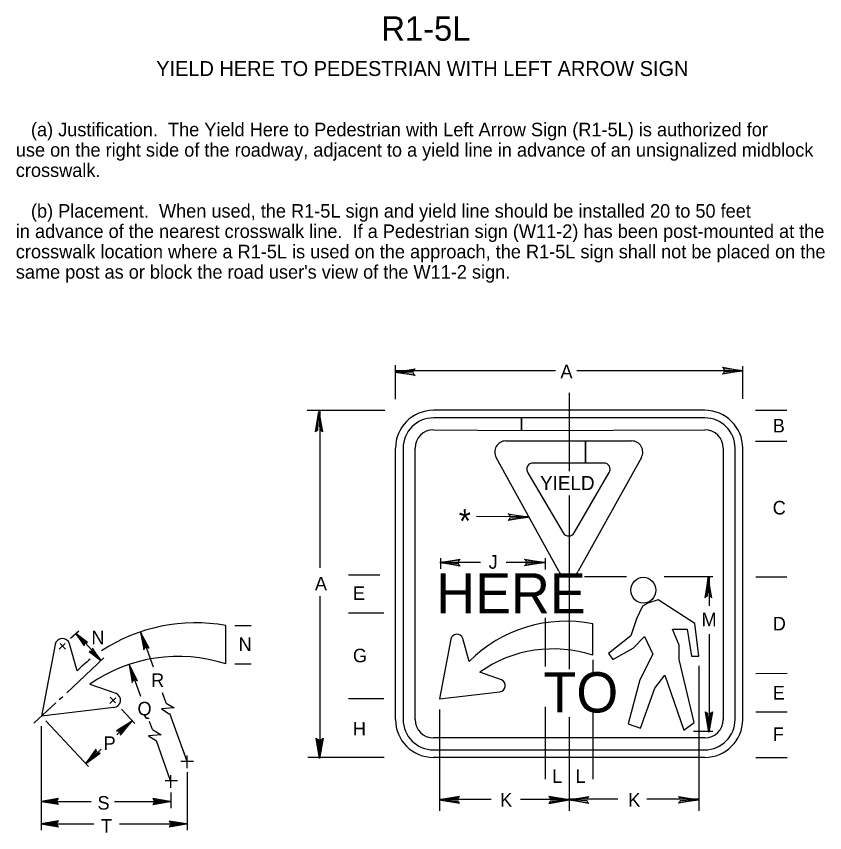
# Model space of a CAD drawing. Extents: x 0.013 to 0.186, y 0.004 to 0.259.
# Drawn here: x 0.0347 to 0.1837, y 0.1087 to 0.2593 of the extents above; entities that cross this region are included whole.
import ezdxf

# ---------------------------------------------------------------- set-up
doc = ezdxf.new("R2010")
doc.units = 0
for name, color, linetype in [('1', 7, 'Continuous'), ('2', 7, 'Continuous'), ('3', 7, 'Continuous')]:
    doc.layers.add(name, color=color, linetype=linetype)

# ---------------------------------------------------------------- blocks, each defined once
blk = doc.blocks.new('RARROW')
at = {"layer": '3'}
for p, q in [((-2.156, 0.28500000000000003), (-2.2665, 0.384625)), ((-2.2665, 0.384625), (0, 0)), ((0, 0), (-2.2665, -0.379125)), ((-2.156, 0.28500000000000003), (-2.075625, 0.12075)), ((0, 0), (-2.156, 0.28500000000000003)), ((-2.14975, -0.2705), (0, 0)), ((-2.075625, 0.12075), (0, 0)), ((0, 0), (-2.074, -0.108)), ((-2.2665, -0.379125), (-2.14975, -0.2705)), ((-2.074, -0.108), (-2.14975, -0.2705))]:
    blk.add_line(p, q, dxfattribs=at)

msp = doc.modelspace()

# ---------------------------------------------------------------- linework, layer by layer
at = {"layer": '1'}
for p, q in [((0.1365621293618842, 0.18985260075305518), (0.1365621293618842, 0.17539631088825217)), ((0.0906959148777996, 0.15757091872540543), (0.0906959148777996, 0.18659299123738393)), ((0.1615621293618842, 0.1866023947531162), (0.11156212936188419, 0.1866023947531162)), ((0.12776248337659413, 0.1852023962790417), (0.11156212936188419, 0.1852023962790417)), ((0.12776248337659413, 0.18290239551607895), (0.12776248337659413, 0.1852023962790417)), ((0.1615621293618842, 0.1852023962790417), (0.12776248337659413, 0.1852023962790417)), ((0.12776248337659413, 0.1852023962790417), (0.12776248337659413, 0.18290239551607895)), ((0.11156212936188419, 0.18300239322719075), (0.12776248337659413, 0.18290239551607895)), ((0.12776248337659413, 0.18290239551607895), (0.1615621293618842, 0.18300239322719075)), ((0.12489039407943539, 0.18096151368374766), (0.13957514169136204, 0.18096151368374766)), ((0.13957514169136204, 0.18096151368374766), (0.13957514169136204, 0.1768695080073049)), ((0.13957514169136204, 0.1768695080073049), (0.13957514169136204, 0.18096151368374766)), ((0.13957514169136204, 0.18096151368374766), (0.14808746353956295, 0.18096151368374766)), ((0.10456212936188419, 0.12960239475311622), (0.10456212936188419, 0.1796023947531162)), ((0.10596212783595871, 0.1796023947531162), (0.10596212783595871, 0.12960239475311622)), ((0.10816213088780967, 0.12960239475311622), (0.10816213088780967, 0.1796023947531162)), ((0.1649621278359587, 0.1796023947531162), (0.1649621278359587, 0.12960239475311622)), ((0.16716213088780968, 0.12960239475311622), (0.16716213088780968, 0.1796023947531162)), ((0.1685621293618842, 0.12960239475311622), (0.1685621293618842, 0.1796023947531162)), ((0.1346517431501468, 0.15693576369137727), (0.12309730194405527, 0.1779277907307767)), ((0.1498773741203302, 0.177922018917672), (0.13823473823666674, 0.15692999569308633)), ((0.13957514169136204, 0.1768695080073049), (0.12993006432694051, 0.1768695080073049)), ((0.1429629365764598, 0.1768695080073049), (0.13957514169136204, 0.1768695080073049)), ((0.12892390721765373, 0.1751062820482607), (0.13548238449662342, 0.16400731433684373)), ((0.13749802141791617, 0.16401299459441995), (0.14397241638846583, 0.17511195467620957)), ((0.1365621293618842, 0.17086639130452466), (0.1365621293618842, 0.1388963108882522)), ((0.11286213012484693, 0.15933980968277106), (0.11286213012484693, 0.15737611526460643)), ((0.13216213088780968, 0.15933980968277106), (0.13216213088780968, 0.15722883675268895)), ((0.16235171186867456, 0.15588100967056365), (0.16235171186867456, 0.1505340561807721)), ((0.0906959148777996, 0.12258233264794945), (0.0906959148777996, 0.15234443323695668)), ((0.13216213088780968, 0.14833527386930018), (0.13216213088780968, 0.13935383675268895)), ((0.07329347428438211, 0.13984812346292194), (0.07329347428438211, 0.14692309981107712)), ((0.1409621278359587, 0.14142676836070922), (0.1409621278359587, 0.14725513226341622)), ((0.04469179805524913, 0.1445622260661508), (0.0461749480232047, 0.14594528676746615)), ((0.045695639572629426, 0.14549832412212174), (0.050360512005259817, 0.14049586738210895)), ((0.059953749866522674, 0.1392708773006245), (0.05764195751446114, 0.14578228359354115)), ((0.11813826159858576, 0.14031910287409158), (0.11695585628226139, 0.14453414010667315)), ((0.16235171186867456, 0.14530286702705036), (0.16235171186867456, 0.1273809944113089)), ((0.04183427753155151, 0.1434092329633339), (0.03933348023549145, 0.13021299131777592)), ((0.04256482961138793, 0.14257878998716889), (0.043664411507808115, 0.14360417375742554)), ((0.04276641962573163, 0.14359910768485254), (0.043747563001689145, 0.14254696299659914)), ((0.04588771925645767, 0.13857995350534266), (0.04448595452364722, 0.14357697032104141)), ((0.11474613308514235, 0.14439435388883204), (0.11266213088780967, 0.13339748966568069)), ((0.04396765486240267, 0.13453443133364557), (0.0508398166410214, 0.14094282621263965)), ((0.1409621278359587, 0.14056803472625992), (0.1409621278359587, 0.13772883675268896)), ((0.05761690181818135, 0.13382880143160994), (0.055511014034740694, 0.1397602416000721)), ((0.1604621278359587, 0.13950189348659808), (0.1604621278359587, 0.11275311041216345)), ((0.12407117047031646, 0.13690389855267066), (0.12009439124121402, 0.13832543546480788)), ((0.048252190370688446, 0.13612652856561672), (0.053024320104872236, 0.1344206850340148)), ((0.06231665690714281, 0.1326155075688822), (0.06165305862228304, 0.13448459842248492)), ((0.11266213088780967, 0.13339748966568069), (0.12377758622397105, 0.1347093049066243)), ((0.037914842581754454, 0.12889009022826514), (0.04193633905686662, 0.1326401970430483)), ((0.042594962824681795, 0.13325437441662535), (0.04322944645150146, 0.13384604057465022)), ((0.05189458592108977, 0.132573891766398), (0.05299416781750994, 0.13359927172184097)), ((0.051968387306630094, 0.1337312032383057), (0.052982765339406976, 0.132643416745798)), ((0.052672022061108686, 0.1317871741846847), (0.03933348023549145, 0.13021299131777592)), ((0.054042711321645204, 0.13150676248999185), (0.05651857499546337, 0.12885172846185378)), ((0.11266213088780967, 0.13141330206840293), (0.11266213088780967, 0.11275311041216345)), ((0.13216213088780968, 0.1319339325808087), (0.13216213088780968, 0.11860383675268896)), ((0.1409621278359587, 0.13131318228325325), (0.1409621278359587, 0.11860383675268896)), ((0.06614082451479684, 0.12184433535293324), (0.06300259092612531, 0.13068349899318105)), ((0.1365621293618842, 0.1300407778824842), (0.1365621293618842, 0.11860383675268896)), ((0.03933348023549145, 0.10920893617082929), (0.03933348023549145, 0.12837398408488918)), ((0.040123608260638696, 0.12936567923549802), (0.04800561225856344, 0.12091326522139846)), ((0.053183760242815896, 0.12677003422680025), (0.056005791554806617, 0.1294016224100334)), ((0.05978366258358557, 0.12772589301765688), (0.05925541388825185, 0.1292137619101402)), ((0.06306558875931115, 0.1184819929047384), (0.060522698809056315, 0.12564431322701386)), ((0.1615621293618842, 0.1262023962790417), (0.11156212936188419, 0.1262023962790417)), ((0.04749282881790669, 0.12146315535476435), (0.0503365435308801, 0.12411496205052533)), ((0.06614082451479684, 0.12184433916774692), (0.0653419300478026, 0.12409451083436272)), ((0.11156212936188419, 0.12400239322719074), (0.1615621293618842, 0.12400239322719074)), ((0.06614082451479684, 0.12064433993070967), (0.06614082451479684, 0.12295720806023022)), ((0.1615621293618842, 0.12260239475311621), (0.11156212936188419, 0.12260239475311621)), ((0.06734082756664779, 0.12184433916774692), (0.06502795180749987, 0.12184433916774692)), ((0.06314082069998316, 0.11699781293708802), (0.06314082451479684, 0.11931068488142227)), ((0.06614082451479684, 0.11988760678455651), (0.06614082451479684, 0.10920893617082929)), ((0.06441310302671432, 0.11827009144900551), (0.06210022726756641, 0.11827009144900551)), ((0.1365621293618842, 0.11860383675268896), (0.1365621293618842, 0.11275311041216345)), ((0.06314082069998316, 0.11610695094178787), (0.06314082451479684, 0.11323927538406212)), ((0.04846923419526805, 0.11440763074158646), (0.03933348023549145, 0.11440763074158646)), ((0.06314082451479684, 0.11440763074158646), (0.05279922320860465, 0.11440763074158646)), ((0.04896923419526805, 0.11028890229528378), (0.03933348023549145, 0.11028890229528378)), ((0.06614082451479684, 0.11028890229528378), (0.05367884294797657, 0.11028890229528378))]:
    msp.add_line(p, q, dxfattribs=at)
for points in [[(0.06231665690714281, 0.1326155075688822), (0.06378179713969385, 0.1317367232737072), (0.06141981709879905, 0.131589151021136), (0.06288038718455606, 0.13064011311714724)], [(0.05978366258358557, 0.12772589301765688), (0.06140349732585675, 0.12675432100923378), (0.05904151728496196, 0.1266067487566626), (0.060522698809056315, 0.12564431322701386)]]:
    msp.add_lwpolyline(points, dxfattribs=at)
for centre, radius, start, end in [((0.11156213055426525, 0.1796023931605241), 0.007, 90, 180), ((0.11156213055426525, 0.1796023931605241), 0.005599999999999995, 90, 180), ((0.16156213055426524, 0.1796023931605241), 0.007, 0, 90), ((0.16156213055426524, 0.1796023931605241), 0.005599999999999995, 0, 90), ((0.11156213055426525, 0.1796023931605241), 0.003400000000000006, 90, 180), ((0.16156213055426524, 0.1796023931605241), 0.003400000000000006, 0, 90), ((0.12489039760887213, 0.17891474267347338), 0.002046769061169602, 89.99999999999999, 208.829273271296), ((0.1480874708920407, 0.17891474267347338), 0.0020467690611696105, 330.9862922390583, 90), ((0.12993006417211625, 0.17570081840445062), 0.0011686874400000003, 90, 210.57922687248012), ((0.14296293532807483, 0.17570081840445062), 0.001168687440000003, 329.74356283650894, 90), ((0.13648854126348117, 0.16460185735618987), 0.0011686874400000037, 210.57922480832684, 329.7435707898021), ((0.13644483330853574, 0.15792271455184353), 0.0020467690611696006, 208.82927195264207, 330.9862956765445), ((0.13610994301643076, 0.12220145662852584), 0.025519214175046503, 79.03913091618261, 134.76826429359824), ((0.067662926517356, 0.11623536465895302), 0.031200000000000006, 79.60307759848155, 123.5783292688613), ((0.04318157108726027, 0.14315390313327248), 0.001371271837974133, 17.969864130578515, 169.26922826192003), ((0.11586887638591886, 0.14418158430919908), 0.0011427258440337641, 17.97008397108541, 169.26922826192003), ((0.13361383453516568, 0.11911439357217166), 0.023491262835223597, 71.771363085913, 125.13531244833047), ((0.067662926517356, 0.11623536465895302), 0.031200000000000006, 128.37705113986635, 134.26062747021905), ((0.06453637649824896, 0.1126638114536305), 0.028560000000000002, 72.14427943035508, 124.76240248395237), ((0.1236436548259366, 0.1358441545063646), 0.001142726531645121, 276.73076526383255, 68.03012939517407), ((0.05251130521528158, 0.13314898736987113), 0.001371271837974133, 276.7307671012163, 68.03013123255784), ((0.11156213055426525, 0.12960239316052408), 0.007, 180, 270), ((0.11156213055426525, 0.12960239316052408), 0.005599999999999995, 180, 270), ((0.11156213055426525, 0.12960239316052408), 0.003400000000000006, 180, 270), ((0.16156213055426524, 0.12960239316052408), 0.007, 270, 0), ((0.16156213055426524, 0.12960239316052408), 0.005599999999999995, 270, 0), ((0.16156213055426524, 0.12960239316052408), 0.003400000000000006, 270, 0)]:
    msp.add_arc(centre, radius, start, end, dxfattribs=at)
at = {"layer": '3'}
for p, q in [((0.10456212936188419, 0.18863001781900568), (0.1045556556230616, 0.19491218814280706)), ((0.16855997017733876, 0.18869598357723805), (0.1685537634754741, 0.19471862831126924)), ((0.13407841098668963, 0.19389563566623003), (0.10455670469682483, 0.19389563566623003)), ((0.16855461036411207, 0.19389563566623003), (0.13799616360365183, 0.19389563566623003)), ((0.10257091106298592, 0.18659696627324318), (0.0883117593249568, 0.1865763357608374)), ((0.17091208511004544, 0.18660481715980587), (0.17667836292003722, 0.18661076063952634)), ((0.1709179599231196, 0.1809048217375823), (0.17668423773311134, 0.18091076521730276)), ((0.1291193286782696, 0.16698701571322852), (0.11946694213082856, 0.1669969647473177)), ((0.12026067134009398, 0.1585568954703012), (0.11276747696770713, 0.15856462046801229)), ((0.13216213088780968, 0.1585446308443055), (0.12493695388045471, 0.15855207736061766)), ((0.09590192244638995, 0.15628990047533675), (0.10166820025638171, 0.1562958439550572)), ((0.14713726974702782, 0.15589695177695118), (0.1394148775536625, 0.15590491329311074)), ((0.16306129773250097, 0.15588054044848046), (0.15410087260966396, 0.15588977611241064)), ((0.17094372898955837, 0.15590483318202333), (0.17671000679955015, 0.1559107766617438)), ((0.10240923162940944, 0.14919930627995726), (0.09590923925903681, 0.14918990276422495)), ((0.0749722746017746, 0.1469248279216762), (0.07796923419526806, 0.14692791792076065)), ((0.07497956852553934, 0.13984985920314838), (0.07796923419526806, 0.13985294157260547)), ((0.17096207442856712, 0.13810484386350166), (0.1767283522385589, 0.13811078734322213)), ((0.10243208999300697, 0.13339932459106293), (0.09593209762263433, 0.13338992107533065)), ((0.170969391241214, 0.13100484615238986), (0.17673566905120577, 0.13101078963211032)), ((0.16303192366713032, 0.1273805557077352), (0.15946108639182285, 0.12738423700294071)), ((0.10244771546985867, 0.12259933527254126), (0.08840434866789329, 0.1225790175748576)), ((0.17097804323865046, 0.12261209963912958), (0.1767443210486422, 0.12261804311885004)), ((0.11266213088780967, 0.1148768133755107), (0.12221763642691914, 0.1148768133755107)), ((0.12757772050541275, 0.1148768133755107), (0.1365621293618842, 0.1148768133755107)), ((0.14554653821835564, 0.1148768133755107), (0.1365621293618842, 0.1148768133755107)), ((0.1604621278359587, 0.1148768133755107), (0.15090662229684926, 0.1148768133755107))]:
    msp.add_line(p, q, dxfattribs=at)
msp.add_lwpolyline([(0.14383864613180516, 0.14177131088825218), (0.14458864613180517, 0.14064631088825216), (0.14833864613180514, 0.14277131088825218), (0.15046364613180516, 0.14489631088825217), (0.15196364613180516, 0.14164631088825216), (0.14958864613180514, 0.1368963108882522), (0.14746364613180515, 0.12877131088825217), (0.14971364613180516, 0.12802131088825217), (0.15233864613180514, 0.13539631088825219), (0.15421364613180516, 0.13777131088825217), (0.15771364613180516, 0.12764631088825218), (0.15958864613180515, 0.12902131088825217), (0.15683864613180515, 0.14064631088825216), (0.15683864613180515, 0.14139631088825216), (0.15683864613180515, 0.14202131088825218), (0.15683864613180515, 0.14214631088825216), (0.15683864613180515, 0.14264631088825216), (0.15683864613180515, 0.14327131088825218), (0.15558864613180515, 0.14627131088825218), (0.15833864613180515, 0.14627131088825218), (0.15908864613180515, 0.14127131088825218), (0.16046364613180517, 0.14127131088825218), (0.15971364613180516, 0.14727131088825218), (0.15296364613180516, 0.15164631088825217), (0.15108864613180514, 0.15102131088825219), (0.15008864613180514, 0.15052131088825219), (0.14896364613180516, 0.14814631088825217), (0.14796364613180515, 0.14502131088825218)], close=True, dxfattribs=at)
msp.add_ellipse((0.150234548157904, 0.15342704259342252), major_axis=(1.4651495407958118e-19, 0.0023927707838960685), ratio=0.9570312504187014, dxfattribs=at)

# ---------------------------------------------------------------- block references
for p, xscale, yscale, rotation in [((0.10446364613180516, 0.19364631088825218), 0.0016545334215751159, 0.0016366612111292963, 179.91708286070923), ((0.16858864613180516, 0.19389631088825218), 0.0016545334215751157, 0.001636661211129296, -0.08291713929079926), ((0.09046364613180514, 0.18639631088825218), 0.0016545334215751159, 0.0016366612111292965, 90.08291713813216), ((0.12908864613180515, 0.1668963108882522), 0.0016545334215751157, 0.001636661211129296, -0.08291713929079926), ((0.11271364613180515, 0.15852131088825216), 0.0016545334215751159, 0.0016366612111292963, 179.91708286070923), ((0.13208864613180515, 0.15852131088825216), 0.0016545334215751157, 0.001636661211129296, -0.08291713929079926), ((0.16221364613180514, 0.1557713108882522), 0.0016545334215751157, -0.0016366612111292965, 89.91708286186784), ((0.045643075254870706, 0.14547572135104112), 0.001195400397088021, -0.0011824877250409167, 133.0254306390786), ((0.0576430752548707, 0.1456007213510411), 0.0014063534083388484, -0.001391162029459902, 109.00511165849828), ((0.0502680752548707, 0.1404757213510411), 0.0011954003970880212, -0.0011824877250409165, -46.961572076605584), ((0.0555180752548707, 0.1396007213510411), 0.0014063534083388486, -0.0013911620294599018, 108.09215472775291), ((0.16233864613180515, 0.12727131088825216), 0.0016545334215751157, 0.0016366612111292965, -89.91708286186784), ((0.0558930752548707, 0.1292257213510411), 0.0014063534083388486, -0.0013911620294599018, 42.08659075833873), ((0.09058864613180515, 0.12239631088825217), 0.0016545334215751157, 0.0016366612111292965, -89.91708286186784), ((0.0475180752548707, 0.1214757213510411), 0.0014063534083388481, -0.0013911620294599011, -134.3521239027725), ((0.0392680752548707, 0.11447572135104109), 0.0014063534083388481, -0.0013911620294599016, -179.9170828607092), ((0.0630180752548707, 0.11447572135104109), 0.0014063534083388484, -0.001391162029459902, 0.08291713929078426), ((0.11258864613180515, 0.11477131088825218), 0.0016545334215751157, -0.001636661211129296, -179.9170828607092), ((0.13658864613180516, 0.11477131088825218), 0.0016545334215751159, -0.0016366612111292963, 0.08291713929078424), ((0.13646364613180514, 0.11477131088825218), 0.0016545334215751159, 0.0016366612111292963, 179.91708286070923), ((0.16046364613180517, 0.11477131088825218), 0.0016545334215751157, 0.001636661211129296, -0.08291713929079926), ((0.0392680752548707, 0.11035072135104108), 0.0014063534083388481, -0.0013911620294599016, -179.9170828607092), ((0.06601807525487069, 0.11035072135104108), 0.0014063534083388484, -0.001391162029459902, 0.08291713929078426)]:
    msp.add_blockref('RARROW', p, dxfattribs=dict(at, xscale=xscale, yscale=yscale, rotation=rotation))

# ---------------------------------------------------------------- texts
at = {"layer": '1'}
for s, height, p in [('R1-5L', 0.0045000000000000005, (0.10196804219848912, 0.25475000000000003)), ('YIELD HERE TO PEDESTRIAN WITH LEFT ARROW SIGN', 0.00275025, (0.060468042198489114, 0.24825)), ('HERE', 0.007413, (0.11208864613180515, 0.14914631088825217)), ('TO', 0.007413, (0.13183864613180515, 0.13089631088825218))]:
    msp.add_text(s, height=height, dxfattribs=at).set_placement(p)
msp.add_text('*', height=0.00432, rotation=2, dxfattribs=at).set_placement((0.11633864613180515, 0.16402131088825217))
at = {"layer": '2'}
for s, p in [('   (a) Justification.  The Yield Here to Pedestrian with Left Arrow Sign (R1-5L) is authorized for', (0.03459304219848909, 0.23712524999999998)), ('use on the right side of the roadway, adjacent to a yield line in advance of an unsignalized midblock', (0.03459304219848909, 0.23337549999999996)), ('crosswalk.', (0.03459304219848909, 0.22962575)), ('   (b) Placement.  When used, the R1-5L sign and yield line should be installed 20 to 50 feet', (0.03459304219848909, 0.22212624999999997)), ('in advance of the nearest crosswalk line.  If a Pedestrian sign (W11-2) has been post-mounted at the', (0.03459304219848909, 0.21837649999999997)), ('crosswalk location where a R1-5L is used on the approach, the R1-5L sign shall not be placed on the ', (0.03459304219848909, 0.21462674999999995)), ("same post as or block the road user's view of the W11-2 sign.", (0.03459304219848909, 0.21087699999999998))]:
    msp.add_text(s, height=0.0024997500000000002, dxfattribs=at).set_placement(p)
at = {"layer": '3'}
for s, rotation, p in [('A', 359.9170833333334, (0.13496364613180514, 0.19252131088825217)), ('B', 359.9170833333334, (0.17408864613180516, 0.1825213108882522)), ('C', 0.08291666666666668, (0.17408864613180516, 0.1673963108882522)), ('J', 0.08291666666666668, (0.12171364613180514, 0.15739631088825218)), ('A', 0.08291666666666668, (0.08971364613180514, 0.15339631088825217)), ('E', 0.08291666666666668, (0.09671364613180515, 0.15164631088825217)), ('M', 0.08291666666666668, (0.16096364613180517, 0.14677131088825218)), ('D', 359.9170833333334, (0.17408864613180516, 0.14602131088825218)), ('N', 0.08291666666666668, (0.0485180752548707, 0.1434757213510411)), ('N', 0.08291666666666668, (0.0756430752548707, 0.1422257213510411)), ('G', 359.9170833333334, (0.09671364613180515, 0.1401463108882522)), ('R', 0.08291666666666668, (0.059518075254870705, 0.1356007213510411)), ('E', 0.08291666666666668, (0.17408864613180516, 0.13327131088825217)), ('Q', 0.08291666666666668, (0.0570180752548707, 0.13035072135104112)), ('H', 0.08291666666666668, (0.09671364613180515, 0.12664631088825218)), ('F', 359.9170833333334, (0.17408864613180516, 0.12564631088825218)), ('P', 0.08291666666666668, (0.050768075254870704, 0.1239757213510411)), ('L', 0.08291666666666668, (0.13346364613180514, 0.11789631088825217)), ('L', 359.9170833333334, (0.13771364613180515, 0.11789631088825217)), ('K', 0.08291666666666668, (0.12383864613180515, 0.11352131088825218)), ('K', 359.9170833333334, (0.14746364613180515, 0.11352131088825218)), ('S', 0.08291666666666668, (0.0496430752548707, 0.11297572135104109)), ('T', 0.08291666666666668, (0.0502680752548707, 0.1087257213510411))]:
    msp.add_text(s, height=0.0024997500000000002, rotation=rotation, dxfattribs=at).set_placement(p)
msp.add_text('YIELD', height=0.0025972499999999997, dxfattribs=at).set_placement((0.13121364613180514, 0.1718963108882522))

doc.saveas('drawing.dxf')
